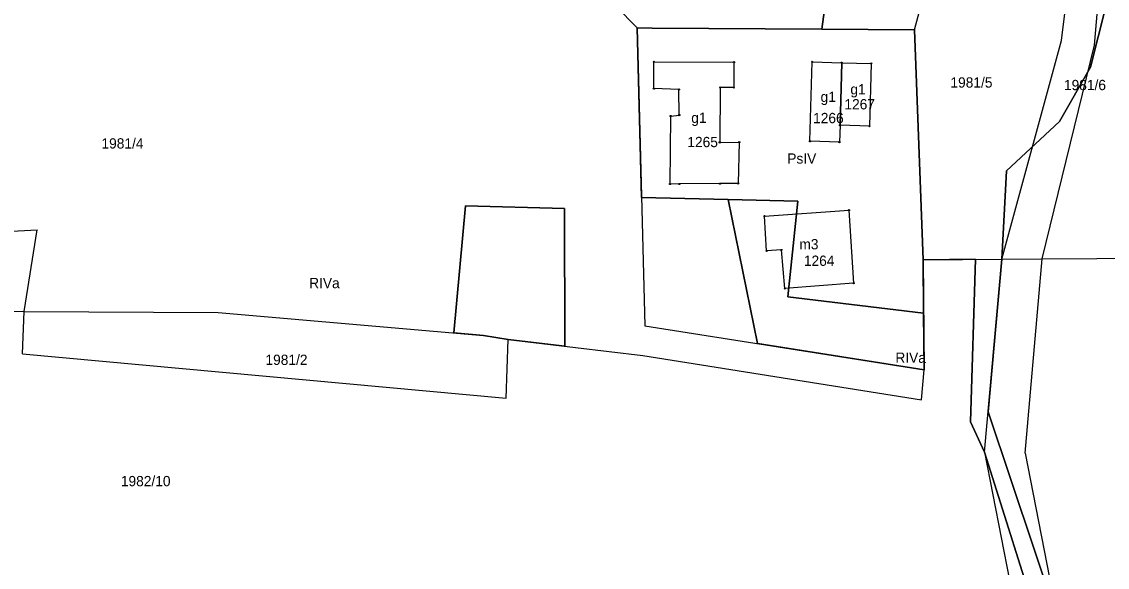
# Model space of a CAD drawing. Extents: x 7498273 to 7499989, y 5499795 to 5500810.
# Drawn here: x 7499038.9 to 7499197.4, y 5499981.8 to 5500061.4 of the extents above; entities that cross this region are included whole.
import ezdxf

# ---------------------------------------------------------------- set-up
doc = ezdxf.new("R2010")
doc.units = 0
for name, color, linetype in [('209-oznaczenie konturu klasyfikacyjnego', 7, 'Continuous'), ('211-numer działki ewidencyjnej', 7, 'Continuous'), ('217-kontur klasyfikacyjny', 7, 'Continuous'), ('218-kontur użytku gruntowego', 7, 'Continuous'), ('219-działka ewidencyjna', 7, 'Continuous'), ('312-budynek ewidencyjny', 7, 'Continuous'), ('312-oznaczenie budynku ewidencyjnego', 7, 'Continuous'), ('312-oznaczenie budynku ewidencyjnego-Atr117', 7, 'Continuous'), ('Punkt budynku', 7, 'Continuous')]:
    doc.layers.add(name, color=color, linetype=linetype)

# ---------------------------------------------------------------- blocks, each defined once
blk = doc.blocks.new('PUNKTBUD')
blk.add_circle((0, 0), 0.09)

msp = doc.modelspace()

# ---------------------------------------------------------------- linework, layer by layer
at = {"layer": '217-kontur klasyfikacyjny'}
for points in [[(7499155.71, 5500060.31), (7499157.9, 5500076.49)], [(7499125.61, 5500063.7), (7499128.74, 5500060.51)], [(7499197.13, 5500063.62), (7499194.92, 5500054.79)], [(7499128.74, 5500060.51), (7499130.91, 5500060.49)], [(7499129.38, 5500035.77), (7499128.74, 5500060.51)], [(7499130.91, 5500060.49), (7499155.71, 5500060.31)], [(7499169.24, 5500060.21), (7499155.71, 5500060.31)], [(7499170.5, 5500026.69), (7499169.24, 5500060.21)], [(7499194.92, 5500054.79), (7499190.4, 5500046.84)], [(7499190.4, 5500046.84), (7499182.67, 5500039.67)], [(7499182.67, 5500039.67), (7499181.97, 5500026.78)], [(7499142, 5500035.46), (7499129.38, 5500035.77)], [(7499146.32, 5500014.46), (7499142, 5500035.46)], [(7499142, 5500035.46), (7499152.21, 5500035.21)], [(7499152.21, 5500035.21), (7499150.72, 5500021.26)], [(7499101.96, 5500016.01), (7499103.66, 5500034.54)], [(7499103.66, 5500034.54), (7499118.11, 5500034.15)], [(7499118.11, 5500034.15), (7499118.16, 5500014.06)], [(7499178.12, 5500026.75), (7499170.5, 5500026.69)], [(7499170.5, 5500026.69), (7499170.55, 5500018.89)], [(7499177.39, 5500003.05), (7499178.12, 5500026.75)], [(7499181.97, 5500026.78), (7499179.96, 5500004.48)], [(7499150.72, 5500021.26), (7499170.55, 5500018.89)], [(7499170.55, 5500018.89), (7499170.61, 5500010.64)], [(7499106.29, 5500015.63), (7499101.96, 5500016.01)], [(7499109.92, 5500015.02), (7499106.29, 5500015.63)], [(7499118.16, 5500014.06), (7499109.92, 5500015.02)], [(7499170.61, 5500010.64), (7499146.32, 5500014.46)], [(7499179.96, 5500004.48), (7499190.12, 5499974.29)], [(7499179.43, 5499998.62), (7499177.39, 5500003.05)], [(7499187.85, 5499971.95), (7499179.43, 5499998.62)]]:
    msp.add_lwpolyline(points, dxfattribs=at)
at = {"layer": '218-kontur użytku gruntowego'}
for points in [[(7499157.9, 5500076.49), (7499155.71, 5500060.31)], [(7499128.74, 5500060.51), (7499125.61, 5500063.7)], [(7499194.92, 5500054.79), (7499197.13, 5500063.62)], [(7499128.74, 5500060.51), (7499129.38, 5500035.77)], [(7499130.91, 5500060.49), (7499128.74, 5500060.51)], [(7499155.71, 5500060.31), (7499130.91, 5500060.49)], [(7499155.71, 5500060.31), (7499169.24, 5500060.21)], [(7499169.24, 5500060.21), (7499170.5, 5500026.69)], [(7499190.4, 5500046.84), (7499194.92, 5500054.79)], [(7499182.67, 5500039.67), (7499190.4, 5500046.84)], [(7499181.97, 5500026.78), (7499182.67, 5500039.67)], [(7499129.38, 5500035.77), (7499142, 5500035.46)], [(7499142, 5500035.46), (7499146.32, 5500014.46)], [(7499152.21, 5500035.21), (7499142, 5500035.46)], [(7499150.72, 5500021.26), (7499152.21, 5500035.21)], [(7499103.66, 5500034.54), (7499101.96, 5500016.01)], [(7499118.11, 5500034.15), (7499103.66, 5500034.54)], [(7499118.16, 5500014.06), (7499118.11, 5500034.15)], [(7499170.5, 5500026.69), (7499178.12, 5500026.75)], [(7499170.55, 5500018.89), (7499170.5, 5500026.69)], [(7499178.12, 5500026.75), (7499177.39, 5500003.05)], [(7499179.96, 5500004.48), (7499181.97, 5500026.78)], [(7499170.55, 5500018.89), (7499150.72, 5500021.26)], [(7499170.61, 5500010.64), (7499170.55, 5500018.89)], [(7499101.96, 5500016.01), (7499106.29, 5500015.63)], [(7499106.29, 5500015.63), (7499109.92, 5500015.02)], [(7499109.92, 5500015.02), (7499118.16, 5500014.06)], [(7499146.32, 5500014.46), (7499170.61, 5500010.64)], [(7499190.12, 5499974.29), (7499179.96, 5500004.48)], [(7499177.39, 5500003.05), (7499179.43, 5499998.62)], [(7499179.43, 5499998.62), (7499187.85, 5499971.95)]]:
    msp.add_lwpolyline(points, dxfattribs=at)
at = {"layer": '219-działka ewidencyjna'}
for points in [[(7499169.24, 5500060.21), (7499173.24, 5500075.29)], [(7499190.67, 5500058.68), (7499191.76, 5500067.35)], [(7499195.5, 5500057.99), (7499196.32, 5500067.68)], [(7499128.74, 5500060.51), (7499169.24, 5500060.21)], [(7499128.74, 5500060.51), (7499129.87, 5500017.05)], [(7499181.97, 5500026.78), (7499190.67, 5500058.68)], [(7499187.87, 5500026.8), (7499195.5, 5500057.99)], [(7499023.4, 5500030.13), (7499041.16, 5500031.06)], [(7499039.25, 5500019.15), (7499041.16, 5500031.06)], [(7499187.87, 5500026.8), (7499227.79, 5500027.07)], [(7499170.5, 5500026.69), (7499181.97, 5500026.78)], [(7499170.5, 5500026.69), (7499170.61, 5500010.64)], [(7499179.43, 5499998.62), (7499181.97, 5500026.78)], [(7499181.97, 5500026.78), (7499187.87, 5500026.8)], [(7499185.39, 5499998.46), (7499187.87, 5500026.8)], [(7499013.38, 5500019.83), (7499039.25, 5500019.15)], [(7499039.02, 5500012.94), (7499039.25, 5500019.15)], [(7499039.25, 5500019.15), (7499067.57, 5500019)], [(7499067.57, 5500019), (7499106.29, 5500015.63)], [(7499129.87, 5500017.05), (7499170.61, 5500010.64)], [(7499106.29, 5500015.63), (7499109.92, 5500015.02)], [(7499109.6, 5500006.5), (7499109.92, 5500015.02)], [(7499109.92, 5500015.02), (7499129.55, 5500012.73)], [(7499039.02, 5500012.94), (7499109.6, 5500006.5)], [(7499129.55, 5500012.73), (7499170.24, 5500006.24)], [(7499170.24, 5500006.24), (7499170.61, 5500010.64)], [(7499179.43, 5499998.62), (7499184.3, 5499973.72)], [(7499185.39, 5499998.46), (7499190.12, 5499974.29)]]:
    msp.add_lwpolyline(points, dxfattribs=at)
at = {"layer": '312-budynek ewidencyjny'}
for points in [[(7499131.16, 5500055.56), (7499142.86, 5500055.5)], [(7499131.18, 5500051.65), (7499131.16, 5500055.56)], [(7499142.86, 5500055.5), (7499142.85, 5500051.81)], [(7499153.96, 5500043.97), (7499154.28, 5500055.56)], [(7499154.28, 5500055.56), (7499158.6, 5500055.44)], [(7499158.6, 5500055.44), (7499158.36, 5500046.31)], [(7499158.36, 5500046.31), (7499158.6, 5500055.44)], [(7499158.6, 5500055.44), (7499162.9, 5500055.33)], [(7499162.9, 5500055.33), (7499162.66, 5500046.18)], [(7499134.83, 5500051.53), (7499131.18, 5500051.65)], [(7499134.88, 5500047.79), (7499134.83, 5500051.53)], [(7499140.85, 5500051.81), (7499140.79, 5500043.8)], [(7499142.85, 5500051.81), (7499140.85, 5500051.81)], [(7499133.63, 5500047.65), (7499134.88, 5500047.79)], [(7499133.54, 5500037.73), (7499133.63, 5500047.65)], [(7499158.36, 5500046.31), (7499158.26, 5500043.85)], [(7499162.66, 5500046.18), (7499158.36, 5500046.31)], [(7499140.79, 5500043.8), (7499143.64, 5500043.83)], [(7499143.64, 5500043.83), (7499143.47, 5500037.82)], [(7499158.26, 5500043.85), (7499153.96, 5500043.97)], [(7499134.89, 5500037.74), (7499133.54, 5500037.73)], [(7499140.83, 5500037.79), (7499134.89, 5500037.74)], [(7499143.47, 5500037.82), (7499140.83, 5500037.79)], [(7499147.32, 5500033.06), (7499159.65, 5500033.9)], [(7499159.65, 5500033.9), (7499160.33, 5500023.26)], [(7499147.63, 5500027.99), (7499147.32, 5500033.06)], [(7499149.79, 5500028.11), (7499147.63, 5500027.99)], [(7499150.3, 5500022.49), (7499149.79, 5500028.11)], [(7499160.33, 5500023.26), (7499150.3, 5500022.49)]]:
    msp.add_lwpolyline(points, dxfattribs=at)

# ---------------------------------------------------------------- block references
at = {"layer": 'Punkt budynku'}
for p in [(7499131.16, 5500055.56), (7499154.28, 5500055.56), (7499142.86, 5500055.5), (7499158.6, 5500055.44), (7499162.9, 5500055.33), (7499131.18, 5500051.65), (7499134.83, 5500051.53), (7499140.85, 5500051.81), (7499142.85, 5500051.81), (7499133.63, 5500047.65), (7499134.88, 5500047.79), (7499158.36, 5500046.31), (7499162.66, 5500046.18), (7499140.79, 5500043.8), (7499143.64, 5500043.83), (7499153.96, 5500043.97), (7499158.26, 5500043.85), (7499133.54, 5500037.73), (7499134.89, 5500037.74), (7499140.83, 5500037.79), (7499143.47, 5500037.82), (7499159.65, 5500033.9), (7499147.32, 5500033.06), (7499147.63, 5500027.99), (7499149.79, 5500028.11), (7499150.3, 5500022.49), (7499160.33, 5500023.26)]:
    msp.add_blockref('PUNKTBUD', p, dxfattribs=at)

# ---------------------------------------------------------------- texts
at = {"layer": '209-oznaczenie konturu klasyfikacyjnego'}
for s, p in [('PsIV', (7499150.65, 5500040.7)), ('RIVa', (7499080.85, 5500022.53)), ('RIVa', (7499166.43, 5500011.64))]:
    msp.add_text(s, height=1.5, dxfattribs=at).set_placement(p)
at = {"layer": '211-numer działki ewidencyjnej'}
for s, p in [('1981/5', (7499174.47, 5500051.8)), ('1981/6', (7499191.04, 5500051.43)), ('1981/4', (7499050.53, 5500042.91)), ('1981/2', (7499074.47, 5500011.33)), ('1982/10', (7499053.36, 5499993.63))]:
    msp.add_text(s, height=1.5, dxfattribs=at).set_placement(p)
at = {"layer": '312-oznaczenie budynku ewidencyjnego'}
for s, p in [('1267', (7499158.99, 5500048.62)), ('1266', (7499154.42, 5500046.61)), ('1265', (7499136.06, 5500043.11)), ('1264', (7499153.07, 5500025.79))]:
    msp.add_text(s, height=1.5, dxfattribs=at).set_placement(p)
at = {"layer": '312-oznaczenie budynku ewidencyjnego-Atr117'}
for s, p in [('g1', (7499155.509, 5500049.71)), ('g1', (7499159.859, 5500050.81)), ('g1', (7499136.629, 5500046.65)), ('m3', (7499152.416, 5500028.2))]:
    msp.add_text(s, height=1.5, dxfattribs=at).set_placement(p)

doc.saveas('drawing.dxf')
